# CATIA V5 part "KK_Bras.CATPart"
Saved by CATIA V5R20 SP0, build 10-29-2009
Part number: skl bras
Bounding box of the stored display mesh (mm): x 500 to 1300, y 0 to 0, z -130 to -90
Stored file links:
  G:\Khaled_CFAO_2011\ST2M\ST2M_GR2\tcorbin\Khaled\CAD_ThinkMOTION\KK_Bras.CATPart
  F:\Thinkmotionperso\assemblage robot\ass_skl_robot.CATProduct
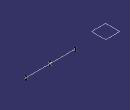
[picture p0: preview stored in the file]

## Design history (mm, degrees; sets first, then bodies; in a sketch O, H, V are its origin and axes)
External parameters (linked from other documents)
  `External.longueur avbras` = 500 mm
  `External.longueur bras` = 800 mm
Set1
  Plane1 "plan_extr_bras": type Offset, RefPlane xy-plane, Offset -110
  Point1 "point_perçage_1": type OnPlane, Support Plane1, H 500, V 0, Direction (1, 0, 0)
  Point2 "point_perçage_2": type OnPlane, Support Plane1, H 900, V 0, Direction (1, 0, 0)
  Point3 "point_perçage_3": type OnPlane, Support Plane1, H 1300 {= `External.longueur avbras` +`External.longueur bras`}, V 0, Direction (1, 0, 0)
  Line1 "droite_long_bras": type PtPt, FirstPoint Point1, SecondPoint Point3
  Line2 "axe_perçage_1": type PtDir, RefPoint Point1, Direction Plane1, Start -20, End 20
  Line3 "axe_perçage_2": type PtDir, RefPoint Point2, Direction Plane1, Start -20, End 20
  Line4 "axe_perçage_3": type PtDir, RefPoint Point3, Direction Plane1, Start -20, End 20
Body1 (main body)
